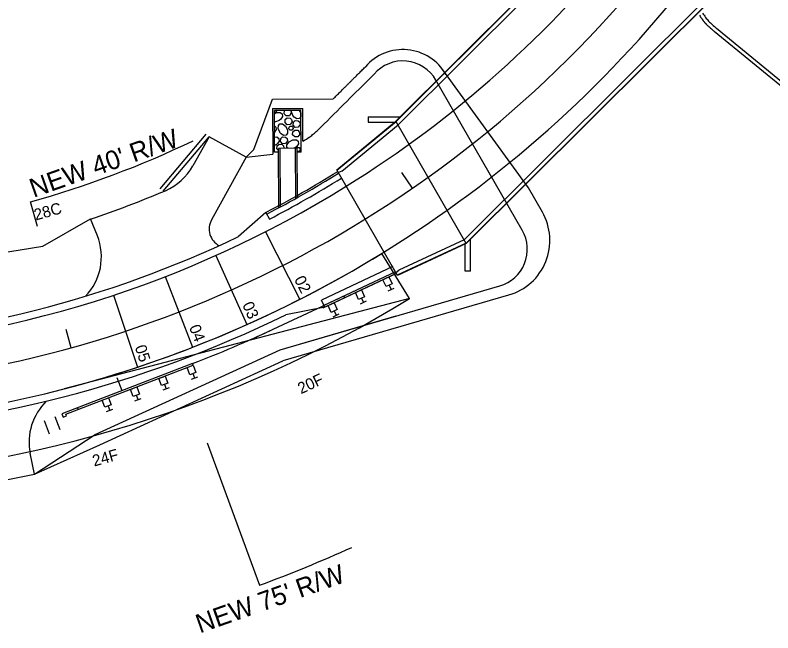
# Model space of a CAD drawing. Extents: x 1539042 to 1541327, y 1198578 to 1200629.
# Drawn here: x 1539977.1 to 1540177.1, y 1199312.4 to 1199475.4 of the extents above; entities that cross this region are included whole.
import ezdxf

# ---------------------------------------------------------------- set-up
doc = ezdxf.new("R2010")
doc.units = 0
for name, color, linetype in [('BR_CONCRETE', 7, 'Continuous'), ('BR_PROPOSED_TRAVELWAY', 7, 'Continuous'), ('RD_HC_CL_Rel', 7, 'Continuous'), ('RD_HC_Data_Tic', 7, 'Continuous'), ('RD_PD_ALT1_TX', 7, 'Continuous'), ('RD_PD_BOC', 7, 'Continuous'), ('RD_PD_CstnLmt', 7, 'Continuous'), ('RD_PD_CstnLmt_TX', 7, 'Continuous'), ('RD_PD_DR_ErosCtrl', 7, 'Continuous'), ('RD_PD_DR_Inlet', 7, 'Continuous'), ('RD_PD_Driveway', 7, 'Continuous'), ('RD_PD_EOP', 7, 'Continuous'), ('RD_PD_Final_TrvlWay', 7, 'Continuous'), ('RD_PD_FOC', 7, 'Continuous'), ('RD_PD_GR', 7, 'Continuous'), ('RD_PD_PaveShd', 7, 'Continuous'), ('RD_PD_RW', 7, 'Continuous'), ('RD_Sketch8', 7, 'Continuous')]:
    doc.layers.add(name, color=color, linetype=linetype)

# ---------------------------------------------------------------- blocks, each defined once
blk = doc.blocks.new('Guardrail_MTBBC2_Transition')
at = {"layer": 'RD_PD_GR'}
for p, q in [((3.875, 3.75), (2.125, 3.75)), ((2.125, 0.5), (2.125, 2.5)), ((2.125, 2.5), (3.875, 2.5)), ((3, 2.5), (3, 3.75)), ((3.875, 2.5), (3.875, 0.5)), ((11.875, 3.75), (10.125, 3.75)), ((10.125, 0.5), (10.125, 2.5)), ((10.125, 2.5), (11.875, 2.5)), ((11, 2.5), (11, 3.75)), ((11.875, 2.5), (11.875, 0.5)), ((19.875, 3.75), (18.125, 3.75)), ((18.125, 0.5), (18.125, 2.5)), ((18.125, 2.5), (19.875, 2.5)), ((19, 2.5), (19, 3.75)), ((19.875, 2.5), (19.875, 0.5)), ((0, 0.5), (0, 0)), ((21.25, 0.5), (0, 0.5)), ((0, 0), (21.25, 0)), ((3.875, 0.5), (2.125, 0.5)), ((11.875, 0.5), (10.125, 0.5)), ((15, 0.5), (15, 0)), ((19.875, 0.5), (18.125, 0.5)), ((21.25, 0), (21.25, 0.5))]:
    blk.add_line(p, q, dxfattribs=at)
blk = doc.blocks.new('Guardrail_MT2_Leading_with_Buffer')
at = {"layer": 'RD_PD_GR'}
for p, q in [((41.94, 2.27), (41.74, 6.01)), ((9.53, 4.27), (7.79, 4.18)), ((8.73, 2.98), (8.66, 4.22)), ((17.52, 4.7), (15.77, 4.61)), ((16.72, 3.41), (16.65, 4.66)), ((25.51, 5.13), (23.76, 5.04)), ((24.7, 3.84), (24.64, 5.09)), ((38.94, 2.11), (38.74, 5.85)), ((1.55, 3.84), (-0.2, 3.74)), ((-0.13, 2.5), (1.61, 2.59)), ((-0.03, 0.5), (-0.13, 2.5)), ((35.92, 2.44), (-0.03, 0.5)), ((0.74, 2.54), (0.67, 3.79)), ((1.61, 2.59), (1.72, 0.59)), ((7.85, 2.93), (9.6, 3.02)), ((7.96, 0.93), (7.85, 2.93)), ((9.6, 3.02), (9.71, 1.03)), ((15.84, 3.36), (17.59, 3.45)), ((15.95, 1.36), (15.84, 3.36)), ((17.59, 3.45), (17.7, 1.46)), ((23.83, 3.79), (25.58, 3.89)), ((23.94, 1.79), (23.83, 3.79)), ((25.58, 3.89), (25.69, 1.89)), ((32.43, 2.25), (32.45, 1.75)), ((36.89, 3), (35.89, 2.94)), ((35.89, 2.94), (35.92, 2.44)), ((36.95, 2), (36.89, 3)), ((1.72, 0.59), (-0.03, 0.5)), ((-0.03, 0.5), (0, 0)), ((0, 0), (36.95, 2)), ((9.71, 1.03), (7.96, 0.93)), ((17.7, 1.46), (15.95, 1.36)), ((20.17, -2.67), (19.97, 1.08)), ((25.69, 1.89), (23.94, 1.79))]:
    blk.add_line(p, q, dxfattribs=at)

msp = doc.modelspace()

# ---------------------------------------------------------------- linework, layer by layer
at = {"layer": 'BR_CONCRETE'}
for p, q in [((1540077.64, 1199447.44), (1540148.21, 1199517.71)), ((1540077.68, 1199447.36), (1540148.25, 1199517.64)), ((1540078.2, 1199446.47), (1540148.77, 1199516.74)), ((1540095.64, 1199416.09), (1540166.22, 1199486.37)), ((1540096.16, 1199415.2), (1540166.73, 1199485.47)), ((1540096.2, 1199415.12), (1540166.77, 1199485.39)), ((1540070.32, 1199448.55), (1540070.31, 1199447.13)), ((1540070.32, 1199448.55), (1540078.74, 1199448.53)), ((1540062.02, 1199434.56), (1540077.64, 1199447.44)), ((1540062.07, 1199434.49), (1540077.68, 1199447.36)), ((1540070.31, 1199447.13), (1540077.25, 1199447.12)), ((1540096.2, 1199415.12), (1540077.64, 1199447.44)), ((1540063.35, 1199434.25), (1540078.2, 1199446.47)), ((1540078.02, 1199406.71), (1540062.02, 1199434.56)), ((1540063.35, 1199434.25), (1540062.45, 1199433.83)), ((1540096.16, 1199415.2), (1540077.98, 1199406.78)), ((1540096.2, 1199415.12), (1540078.02, 1199406.71)), ((1540095.64, 1199416.09), (1540078.39, 1199408.08)), ((1540095.87, 1199407.8), (1540095.88, 1199414.94)), ((1540097.29, 1199407.8), (1540097.3, 1199416.22)), ((1540077.61, 1199407.44), (1540078.39, 1199408.08)), ((1540097.29, 1199407.8), (1540095.87, 1199407.8))]:
    msp.add_line(p, q, dxfattribs=at)
at = {"layer": 'BR_PROPOSED_TRAVELWAY'}
for radius, start in [(290, 301.8034), (310, 301.6792)]:
    msp.add_arc((1539911.68, 1199676.68), radius, start, 321.687, dxfattribs=at)
at = {"layer": 'RD_HC_CL_Rel'}
msp.add_arc((1539911.68, 1199676.68), 300, 272.8619, 321.687, dxfattribs=at)
at = {"layer": 'RD_HC_Data_Tic'}
for p, q in [((1540082.05, 1199429.75), (1540079.22, 1199433.87)), ((1539991.88, 1199387.6), (1539990.55, 1199392.42))]:
    msp.add_line(p, q, dxfattribs=at)
at = {"layer": 'RD_PD_ALT1_TX'}
for p, q in [((1540043.18, 1199418.21), (1540052.25, 1199400.38)), ((1540030.1, 1199411.96), (1540038.27, 1199393.7)), ((1540016.72, 1199406.37), (1540023.96, 1199387.73)), ((1540003.08, 1199401.46), (1540009.38, 1199382.48))]:
    msp.add_line(p, q, dxfattribs=at)
at = {"layer": 'RD_PD_BOC'}
msp.add_line((1540077.7, 1199407.2), (1540058.84, 1199398.34), dxfattribs=at)
msp.add_arc((1539911.68, 1199676.68), 285.5, 297.4563, 301.8338, dxfattribs=at)
at = {"layer": 'RD_PD_CstnLmt'}
for p, q in [((1540188.28, 1199450.52), (1540162.25, 1199471.89)), ((1540110.97, 1199418.61), (1540088.2, 1199458.25)), ((1540045.05, 1199450.73), (1540053.04, 1199450.77)), ((1540045.05, 1199450.73), (1540045.11, 1199438.67)), ((1540053.09, 1199442.1), (1540053.04, 1199450.77)), ((1540016.16, 1199428.93), (1540028.3, 1199443.29)), ((1540038.09, 1199437.87), (1540045.11, 1199438.67)), ((1539984.44, 1199414.44), (1539997.05, 1199421.59)), ((1539939.79, 1199407.26), (1539984.44, 1199414.44)), ((1540047.06, 1199387.09), (1540105.07, 1199403.96)), ((1540047.06, 1199387.09), (1540077.73, 1199396.01)), ((1539998.22, 1199364.74), (1540047.06, 1199387.09)), ((1539982.23, 1199354.27), (1539998.22, 1199364.74))]:
    msp.add_line(p, q, dxfattribs=at)
for centre, radius, start, end in [((1540079.49, 1199453.31), 10.01, 29.556, 139.5224), ((1540102.31, 1199413.59), 10.02, 285.9823, 30.0801)]:
    msp.add_arc(centre, radius, start, end, dxfattribs=at)
for points in [[(1540158.58, 1199475.93), (1540159.36, 1199474.81), (1540160.18, 1199473.82), (1540161.14, 1199472.91), (1540162.25, 1199471.89)], [(1540053.09, 1199442.1), (1540054.89, 1199443.3), (1540055.9, 1199444.06), (1540056.86, 1199444.9), (1540057.78, 1199445.79), (1540058.68, 1199446.69), (1540065.5, 1199453.47), (1540071.87, 1199459.81)]]:
    msp.add_spline(points, degree=3, dxfattribs=at)
at = {"layer": 'RD_PD_DR_ErosCtrl'}
for p, q in [((1540187.64, 1199449.75), (1540161.61, 1199471.12)), ((1540112.6, 1199429.82), (1540090.02, 1199460.95)), ((1540040.11, 1199439.91), (1540045.03, 1199453.23)), ((1540045.03, 1199453.23), (1540061.09, 1199453.32)), ((1540015.4, 1199429.57), (1540027.54, 1199443.94)), ((1540038.09, 1199437.87), (1540040.11, 1199439.91)), ((1540116.29, 1199423.41), (1540112.6, 1199429.82)), ((1540047.9, 1199384.21), (1540107.47, 1199401.53)), ((1539999.47, 1199362.02), (1540047.82, 1199384.14)), ((1539982.23, 1199354.27), (1539999.47, 1199362.02))]:
    msp.add_line(p, q, dxfattribs=at)
for centre, radius, start, end in [((1540079.49, 1199453.31), 13.01, 29.556, 139.5224), ((1540103.28, 1199415.94), 15, 286.2163, 29.8783)]:
    msp.add_arc(centre, radius, start, end, dxfattribs=at)
for points, degree in [([(1540157.76, 1199475.36), (1540157.89, 1199475.17), (1540158.09, 1199474.89), (1540158.32, 1199474.56), (1540158.43, 1199474.4), (1540158.49, 1199474.32), (1540158.52, 1199474.28), (1540158.53, 1199474.26), (1540158.54, 1199474.25), (1540158.54, 1199474.24), (1540158.54, 1199474.24), (1540158.54, 1199474.24), (1540158.54, 1199474.24), (1540158.54, 1199474.24), (1540158.54, 1199474.24), (1540158.62, 1199474.14), (1540158.69, 1199474.03), (1540158.85, 1199473.83), (1540158.93, 1199473.73), (1540159.09, 1199473.52), (1540159.18, 1199473.42), (1540159.32, 1199473.27), (1540159.37, 1199473.22), (1540159.43, 1199473.16), (1540159.44, 1199473.15), (1540159.47, 1199473.12), (1540159.48, 1199473.11), (1540159.48, 1199473.11), (1540159.48, 1199473.11), (1540159.48, 1199473.11), (1540159.48, 1199473.11), (1540159.48, 1199473.11), (1540159.48, 1199473.11), (1540159.49, 1199473.11), (1540159.51, 1199473.08), (1540159.53, 1199473.06), (1540159.72, 1199472.88), (1540159.89, 1199472.72), (1540160.14, 1199472.48), (1540160.23, 1199472.4), (1540160.35, 1199472.28), (1540160.4, 1199472.24), (1540160.44, 1199472.2), (1540160.45, 1199472.19), (1540160.46, 1199472.18), (1540160.46, 1199472.18), (1540160.47, 1199472.18), (1540160.47, 1199472.18), (1540160.47, 1199472.18), (1540160.48, 1199472.17), (1540160.51, 1199472.14), (1540160.88, 1199471.8), (1540161.24, 1199471.47), (1540161.57, 1199471.16)], 3), ([(1540061.09, 1199453.32), (1540063.98, 1199456.19), (1540066.87, 1199459.06), (1540069.76, 1199461.94)], 2)]:
    msp.add_open_spline(points, degree=degree, dxfattribs=at)
at = {"layer": 'RD_PD_DR_Inlet'}
for p, q in [((1540052.55, 1199450.27), (1540045.55, 1199450.23)), ((1540045.61, 1199439.23), (1540045.55, 1199450.23)), ((1540046.1, 1199450.23), (1540046.12, 1199450.14)), ((1540052.61, 1199439.27), (1540052.55, 1199450.27)), ((1540046.04, 1199445.2), (1540045.58, 1199444.55)), ((1540045.94, 1199441.14), (1540045.6, 1199441)), ((1540046.61, 1199439.23), (1540045.61, 1199439.23)), ((1540051.6, 1199440.26), (1540046.6, 1199440.23)), ((1540046.69, 1199424.55), (1540046.6, 1199440.23)), ((1540047.19, 1199424.82), (1540047.1, 1199440.24)), ((1540048.08, 1199440.3), (1540048.04, 1199440.24)), ((1540051.07, 1199440.41), (1540050.69, 1199440.26)), ((1540051.18, 1199427.01), (1540051.1, 1199440.26)), ((1540051.68, 1199427.29), (1540051.6, 1199440.26)), ((1540052.61, 1199439.27), (1540051.61, 1199439.26))]:
    msp.add_line(p, q, dxfattribs=at)
for points in [[(1540046.12, 1199450.14), (1540045.82, 1199449.7), (1540045.55, 1199449.69)], [(1540045.55, 1199449.36), (1540046.19, 1199449.69), (1540047.1, 1199449.71), (1540047.61, 1199449.35), (1540047.67, 1199448.62), (1540047.25, 1199447.97), (1540046.78, 1199447.59)], [(1540050, 1199449.57), (1540049.5, 1199448.85), (1540048.69, 1199448.8), (1540048.13, 1199449.38), (1540048.2, 1199450.19), (1540048.27, 1199450.24)], [(1540049.81, 1199450.25), (1540049.87, 1199450.19), (1540050, 1199449.57)], [(1540050.43, 1199448.91), (1540050.05, 1199449.85), (1540050.08, 1199450.25)], [(1540052.13, 1199450.27), (1540052.5, 1199449.54), (1540052.52, 1199448.63), (1540052.16, 1199448.11), (1540051.44, 1199448.06), (1540050.79, 1199448.47), (1540050.4, 1199448.95)], [(1540046.82, 1199447.61), (1540045.88, 1199447.23), (1540045.56, 1199447.26)], [(1540046.95, 1199444.5), (1540046.57, 1199445.44), (1540046.64, 1199446.3), (1540047.03, 1199446.72), (1540047.73, 1199446.71), (1540048.53, 1199446.09), (1540049.02, 1199445.12), (1540049.04, 1199444.21), (1540048.68, 1199443.7), (1540047.95, 1199443.65), (1540047.3, 1199444.06), (1540046.92, 1199444.53)], [(1540050.23, 1199447.21), (1540049.73, 1199446.49), (1540048.93, 1199446.44), (1540048.37, 1199447.02), (1540048.44, 1199447.83), (1540048.94, 1199448.25), (1540049.73, 1199448.19), (1540050.11, 1199447.83), (1540050.23, 1199447.21)], [(1540052.37, 1199446.51), (1540051.87, 1199445.79), (1540051.06, 1199445.74), (1540050.5, 1199446.32), (1540050.58, 1199447.13), (1540051.07, 1199447.55), (1540051.87, 1199447.49), (1540052.24, 1199447.13), (1540052.37, 1199446.51)], [(1540045.57, 1199446.15), (1540045.91, 1199445.83), (1540046.04, 1199445.2)], [(1540050.5, 1199445.48), (1540050.2, 1199445.05), (1540049.72, 1199445.02), (1540049.38, 1199445.36), (1540049.43, 1199445.85), (1540049.72, 1199446.1), (1540050.2, 1199446.07), (1540050.43, 1199445.85), (1540050.5, 1199445.48)], [(1540052.24, 1199444.02), (1540051.74, 1199443.3), (1540050.94, 1199443.25), (1540050.37, 1199443.83), (1540050.45, 1199444.64), (1540050.94, 1199445.06), (1540051.74, 1199445), (1540052.12, 1199444.64), (1540052.24, 1199444.02)], [(1540045.59, 1199443.22), (1540046.22, 1199443.24), (1540046.73, 1199442.87), (1540046.79, 1199442.15), (1540046.37, 1199441.5), (1540045.9, 1199441.12)], [(1540049.02, 1199442.2), (1540048.52, 1199441.48), (1540047.71, 1199441.43), (1540047.15, 1199442.01), (1540047.23, 1199442.82), (1540047.72, 1199443.24), (1540048.52, 1199443.18), (1540048.89, 1199442.82), (1540049.02, 1199442.2)], [(1540046.61, 1199439.7), (1540046.21, 1199440.1), (1540046.29, 1199440.92), (1540046.78, 1199441.33), (1540047.58, 1199441.28), (1540047.95, 1199440.92), (1540048.08, 1199440.3)], [(1540049.1, 1199440.25), (1540048.84, 1199440.49), (1540048.85, 1199441.19), (1540049.47, 1199441.99), (1540050.44, 1199442.48), (1540051.35, 1199442.5), (1540051.86, 1199442.14), (1540051.92, 1199441.42), (1540051.5, 1199440.77), (1540051.03, 1199440.38)], [(1540051.33, 1199440.26), (1540051.6, 1199440.48), (1540052.08, 1199440.45), (1540052.3, 1199440.24), (1540052.38, 1199439.86)], [(1540052.38, 1199439.86), (1540052.08, 1199439.43), (1540051.61, 1199439.4)]]:
    msp.add_lwpolyline(points, dxfattribs=at)
at = {"layer": 'RD_PD_Driveway'}
for p, q in [((1540028.3, 1199443.29), (1540024.04, 1199435.61)), ((1540038.09, 1199437.87), (1540028.3, 1199443.29)), ((1540038.09, 1199437.87), (1540028.96, 1199421.37)), ((1539998.82, 1199417.18), (1539997.05, 1199421.59)), ((1539982.23, 1199354.27), (1539981.11, 1199359.78)), ((1539972.43, 1199352.28), (1539982.23, 1199354.27))]:
    msp.add_line(p, q, dxfattribs=at)
for centre, radius, start, end in [((1540010.92, 1199442.87), 15, 292.9975, 331.0401), ((1539911.68, 1199676.68), 269, 288.5032, 292.9975), ((1540033.34, 1199418.95), 5, 151.0401, 241.7367), ((1539984.89, 1199411.6), 15, 316.1357, 21.8033), ((1539995.81, 1199362.76), 15, 134.2625, 191.4743)]:
    msp.add_arc(centre, radius, start, end, dxfattribs=at)
at = {"layer": 'RD_PD_EOP'}
for p, q in [((1540043.32, 1199423.34), (1540044.24, 1199421.57)), ((1540076.84, 1199409.01), (1540057.99, 1199400.15)), ((1540058.84, 1199398.34), (1540057.99, 1199400.15))]:
    msp.add_line(p, q, dxfattribs=at)
msp.add_arc((1539911.68, 1199676.68), 287.5, 297.4565, 301.8202, dxfattribs=at)
at = {"layer": 'RD_PD_Final_TrvlWay'}
for radius, end in [(290, 301.8034), (310, 301.6792)]:
    msp.add_arc((1539911.68, 1199676.68), radius, 272.8619, end, dxfattribs=at)
at = {"layer": 'RD_PD_FOC'}
msp.add_line((1540077.48, 1199407.65), (1540058.63, 1199398.79), dxfattribs=at)
msp.add_arc((1539911.68, 1199676.68), 286, 297.4563, 301.8303, dxfattribs=at)
at = {"layer": 'RD_PD_GR'}
msp.add_line((1540045.24, 1199392.5), (1540058.25, 1199398.61), dxfattribs=at)
for start in [290.9523, 293.7998]:
    msp.add_arc((1539911.68, 1199676.68), 314, start, 295.1711, dxfattribs=at)
at = {"layer": 'RD_PD_PaveShd'}
for p, q in [((1540043.32, 1199423.34), (1540036.08, 1199416.93)), ((1540058.84, 1199398.34), (1540048.59, 1199396.32))]:
    msp.add_line(p, q, dxfattribs=at)
for radius, end in [(288, 295.5911), (312, 296.0265)]:
    msp.add_arc((1539911.68, 1199676.68), radius, 272.8619, end, dxfattribs=at)
at = {"layer": 'RD_PD_RW'}
for p, q in [((1539983.01, 1199419.59), (1539981.19, 1199426.14)), ((1540027.79, 1199362.47), (1540041.66, 1199324.93))]:
    msp.add_line(p, q, dxfattribs=at)
for radius, start, end in [(260, 285.5054, 295.6117), (375, 290.28, 294.3056)]:
    msp.add_arc((1539911.68, 1199676.68), radius, start, end, dxfattribs=at)
at = {"layer": 'RD_Sketch8'}
for q in [(1540073.89, 1199412.5), (1539990.06, 1199376.75)]:
    msp.add_line((1540081.21, 1199400.57), q, dxfattribs=at)
for radius, start in [(310, 284.6446), (324, 272.8619)]:
    msp.add_arc((1539911.68, 1199676.68), radius, start, 301.5493, dxfattribs=at)

# ---------------------------------------------------------------- block references
at = {"layer": 'RD_PD_GR'}
for name, p, rotation in [('Guardrail_MTBBC2_Transition', (1540077.48, 1199407.65), -154.8289364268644), ('Guardrail_MT2_Leading_with_Buffer', (1540023.97, 1199383.44), -162.1417156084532)]:
    msp.add_blockref(name, p, dxfattribs=dict(at, rotation=rotation))

# ---------------------------------------------------------------- texts
at = {"layer": 'RD_PD_ALT1_TX'}
for s, rotation, p in [('02', 296.9645, (1540050.69, 1199405.66)), ('03', 294.0997, (1540037.01, 1199398.95)), ('04', 291.235, (1540022.98, 1199393.03)), ('05', 288.3702, (1540008.67, 1199387.79))]:
    msp.add_text(s, height=3, rotation=rotation, dxfattribs=at).set_placement(p)
at = {"layer": 'RD_PD_CstnLmt_TX'}
for s, rotation, p in [('28C', 15.5054, (1539982.57, 1199421.18)), ('20F', 25.0547, (1540052.57, 1199375.31)), ('24F', 15.5054, (1539997.98, 1199356.24))]:
    msp.add_text(s, height=3, rotation=rotation, dxfattribs=at).set_placement(p)
at = {"layer": 'RD_PD_RW'}
for s, p in [("NEW 40' R/W", (1539981.99, 1199427.16)), ("NEW 75' R/W", (1540025.87, 1199312.17))]:
    msp.add_text(s, height=5, rotation=19.4514, dxfattribs=at).set_placement(p)

doc.saveas('drawing.dxf')
